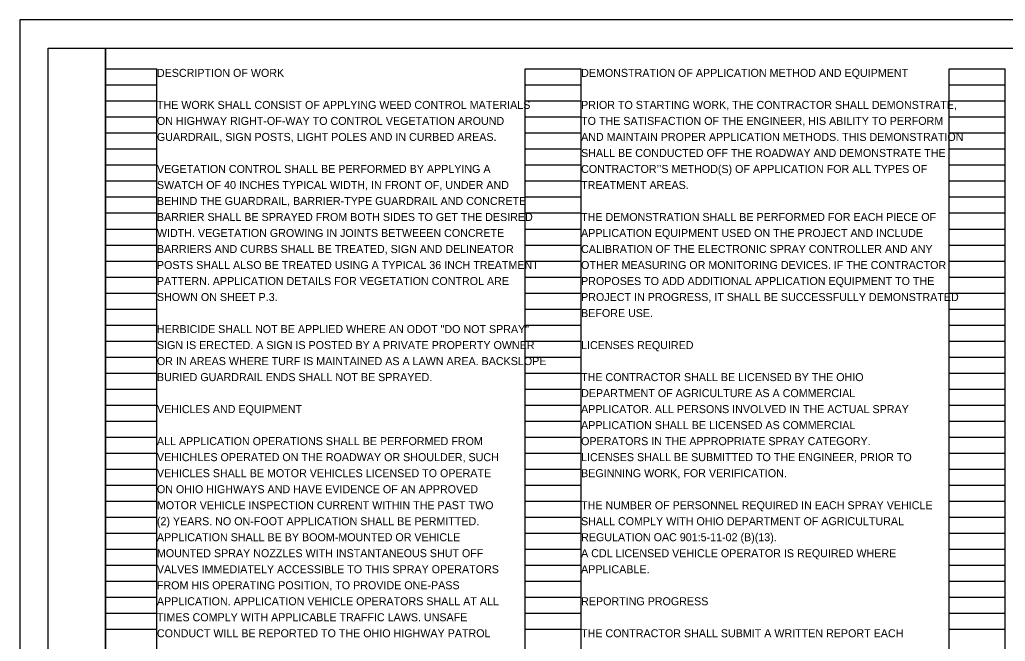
# Model space of a CAD drawing. Extents: x 0 to 34, y 0 to 22.
# Drawn here: x 0 to 17.24, y 11.13 to 22 of the extents above; entities that cross this region are included whole.
import ezdxf

# ---------------------------------------------------------------- set-up
doc = ezdxf.new("R2010")
doc.units = 0
for name, color, linetype in [('SH_Border', 7, 'Continuous'), ('SH_Cut_Line', 7, 'Continuous'), ('SH_Data', 7, 'Continuous'), ('SH_Text', 7, 'Continuous')]:
    doc.layers.add(name, color=color, linetype=linetype)

msp = doc.modelspace()

# ---------------------------------------------------------------- linework, layer by layer
at = {"layer": 'SH_Border'}
for points in [[(0.5, 21.5), (1.5, 21.5), (1.5, 0.5), (0.5, 0.5)], [(1.5, 21.5), (33.5, 21.5), (33.5, 0.5), (1.5, 0.5)]]:
    msp.add_lwpolyline(points, close=True, dxfattribs=at)
at = {"layer": 'SH_Cut_Line'}
msp.add_lwpolyline([(0, 0), (34, 0), (34, 22), (0, 22)], close=True, dxfattribs=at)
at = {"layer": 'SH_Data'}
for p, q in [((1.5, 0.98), (1.5, 21.14)), ((1.5, 21.14), (2.4, 21.14)), ((2.4, 0.98), (2.4, 21.14)), ((8.84, 0.98), (8.84, 21.14)), ((8.84, 21.14), (9.82, 21.14)), ((9.82, 0.98), (9.82, 21.14)), ((16.26, 0.98), (16.26, 21.14)), ((16.26, 21.14), (17.24, 21.14)), ((17.24, 0.98), (17.24, 21.14)), ((1.5, 20.86), (2.4, 20.86)), ((8.84, 20.86), (9.82, 20.86)), ((16.26, 20.86), (17.24, 20.86)), ((1.5, 20.58), (2.4, 20.58)), ((8.84, 20.58), (9.82, 20.58)), ((16.26, 20.58), (17.24, 20.58)), ((1.5, 20.3), (2.4, 20.3)), ((8.84, 20.3), (9.82, 20.3)), ((16.26, 20.3), (17.24, 20.3)), ((1.5, 20.02), (2.4, 20.02)), ((8.84, 20.02), (9.82, 20.02)), ((16.26, 20.02), (17.24, 20.02)), ((1.5, 19.74), (2.4, 19.74)), ((8.84, 19.74), (9.82, 19.74)), ((16.26, 19.74), (17.24, 19.74)), ((1.5, 19.46), (2.4, 19.46)), ((8.84, 19.46), (9.82, 19.46)), ((16.26, 19.46), (17.24, 19.46)), ((1.5, 19.18), (2.4, 19.18)), ((8.84, 19.18), (9.82, 19.18)), ((16.26, 19.18), (17.24, 19.18)), ((1.5, 18.9), (2.4, 18.9)), ((8.84, 18.9), (9.82, 18.9)), ((16.26, 18.9), (17.24, 18.9)), ((1.5, 18.62), (2.4, 18.62)), ((8.84, 18.62), (9.82, 18.62)), ((16.26, 18.62), (17.24, 18.62)), ((1.5, 18.34), (2.4, 18.34)), ((8.84, 18.34), (9.82, 18.34)), ((16.26, 18.34), (17.24, 18.34)), ((1.5, 18.06), (2.4, 18.06)), ((8.84, 18.06), (9.82, 18.06)), ((16.26, 18.06), (17.24, 18.06)), ((1.5, 17.78), (2.4, 17.78)), ((8.84, 17.78), (9.82, 17.78)), ((16.26, 17.78), (17.24, 17.78)), ((1.5, 17.5), (2.4, 17.5)), ((8.84, 17.5), (9.82, 17.5)), ((16.26, 17.5), (17.24, 17.5)), ((1.5, 17.22), (2.4, 17.22)), ((8.84, 17.22), (9.82, 17.22)), ((16.26, 17.22), (17.24, 17.22)), ((1.5, 16.94), (2.4, 16.94)), ((8.84, 16.94), (9.82, 16.94)), ((16.26, 16.94), (17.24, 16.94)), ((1.5, 16.66), (2.4, 16.66)), ((8.84, 16.66), (9.82, 16.66)), ((16.26, 16.66), (17.24, 16.66)), ((1.5, 16.38), (2.4, 16.38)), ((8.84, 16.38), (9.82, 16.38)), ((16.26, 16.38), (17.24, 16.38)), ((1.5, 16.1), (2.4, 16.1)), ((8.84, 16.1), (9.82, 16.1)), ((16.26, 16.1), (17.24, 16.1)), ((1.5, 15.82), (2.4, 15.82)), ((8.84, 15.82), (9.82, 15.82)), ((16.26, 15.82), (17.24, 15.82)), ((1.5, 15.54), (2.4, 15.54)), ((8.84, 15.54), (9.82, 15.54)), ((16.26, 15.54), (17.24, 15.54)), ((1.5, 15.26), (2.4, 15.26)), ((8.84, 15.26), (9.82, 15.26)), ((16.26, 15.26), (17.24, 15.26)), ((1.5, 14.98), (2.4, 14.98)), ((8.84, 14.98), (9.82, 14.98)), ((16.26, 14.98), (17.24, 14.98)), ((1.5, 14.7), (2.4, 14.7)), ((8.84, 14.7), (9.82, 14.7)), ((16.26, 14.7), (17.24, 14.7)), ((1.5, 14.42), (2.4, 14.42)), ((8.84, 14.42), (9.82, 14.42)), ((16.26, 14.42), (17.24, 14.42)), ((1.5, 14.14), (2.4, 14.14)), ((8.84, 14.14), (9.82, 14.14)), ((16.26, 14.14), (17.24, 14.14)), ((1.5, 13.86), (2.4, 13.86)), ((8.84, 13.86), (9.82, 13.86)), ((16.26, 13.86), (17.24, 13.86)), ((1.5, 13.58), (2.4, 13.58)), ((8.84, 13.58), (9.82, 13.58)), ((16.26, 13.58), (17.24, 13.58)), ((1.5, 13.3), (2.4, 13.3)), ((8.84, 13.3), (9.82, 13.3)), ((16.26, 13.3), (17.24, 13.3)), ((1.5, 13.02), (2.4, 13.02)), ((8.84, 13.02), (9.82, 13.02)), ((16.26, 13.02), (17.24, 13.02)), ((1.5, 12.74), (2.4, 12.74)), ((8.84, 12.74), (9.82, 12.74)), ((16.26, 12.74), (17.24, 12.74)), ((1.5, 12.46), (2.4, 12.46)), ((8.84, 12.46), (9.82, 12.46)), ((16.26, 12.46), (17.24, 12.46)), ((1.5, 12.18), (2.4, 12.18)), ((8.84, 12.18), (9.82, 12.18)), ((16.26, 12.18), (17.24, 12.18)), ((1.5, 11.9), (2.4, 11.9)), ((8.84, 11.9), (9.82, 11.9)), ((16.26, 11.9), (17.24, 11.9)), ((1.5, 11.62), (2.4, 11.62)), ((8.84, 11.62), (9.82, 11.62)), ((16.26, 11.62), (17.24, 11.62)), ((1.5, 11.34), (2.4, 11.34)), ((8.84, 11.34), (9.82, 11.34)), ((16.26, 11.34), (17.24, 11.34))]:
    msp.add_line(p, q, dxfattribs=at)

# ---------------------------------------------------------------- texts
at = {"layer": 'SH_Text'}
for s, p in [('DESCRIPTION OF WORK', (2.4, 21)), ('DEMONSTRATION OF APPLICATION METHOD AND EQUIPMENT', (9.82, 21)), ('THE WORK SHALL CONSIST OF APPLYING WEED CONTROL MATERIALS', (2.4, 20.44)), ('PRIOR TO STARTING WORK, THE CONTRACTOR SHALL DEMONSTRATE,', (9.82, 20.44)), ('ON HIGHWAY RIGHT-OF-WAY TO CONTROL VEGETATION AROUND', (2.4, 20.16)), ('TO THE SATISFACTION OF THE ENGINEER, HIS ABILITY TO PERFORM', (9.82, 20.16)), ('GUARDRAIL, SIGN POSTS, LIGHT POLES AND IN CURBED AREAS.', (2.4, 19.88)), ('AND MAINTAIN PROPER APPLICATION METHODS. THIS DEMONSTRATION', (9.82, 19.88)), ('SHALL BE CONDUCTED OFF THE ROADWAY AND DEMONSTRATE THE', (9.82, 19.6)), ('VEGETATION CONTROL SHALL BE PERFORMED BY APPLYING A ', (2.4, 19.32)), ('CONTRACTOR’’S METHOD(S) OF APPLICATION FOR ALL TYPES OF', (9.82, 19.32)), ('SWATCH OF 40 INCHES TYPICAL WIDTH, IN FRONT OF, UNDER AND', (2.4, 19.04)), ('TREATMENT AREAS.', (9.82, 19.04)), ('BEHIND THE GUARDRAIL, BARRIER-TYPE GUARDRAIL AND CONCRETE', (2.4, 18.76)), ('BARRIER SHALL BE SPRAYED FROM BOTH SIDES TO GET THE DESIRED', (2.4, 18.48)), ('THE DEMONSTRATION SHALL BE PERFORMED FOR EACH PIECE OF', (9.82, 18.48)), ('WIDTH. VEGETATION GROWING IN JOINTS BETWEEEN CONCRETE', (2.4, 18.2)), ('APPLICATION EQUIPMENT USED ON THE PROJECT AND INCLUDE', (9.82, 18.2)), ('BARRIERS AND CURBS SHALL BE TREATED, SIGN AND DELINEATOR', (2.4, 17.92)), ('CALIBRATION OF THE ELECTRONIC SPRAY CONTROLLER AND ANY', (9.82, 17.92)), ('POSTS SHALL ALSO BE TREATED USING A TYPICAL 36 INCH TREATMENT', (2.4, 17.64)), ('OTHER MEASURING OR MONITORING DEVICES. IF THE CONTRACTOR ', (9.82, 17.64)), ('PATTERN. APPLICATION DETAILS FOR VEGETATION CONTROL ARE ', (2.4, 17.36)), ('PROPOSES TO ADD ADDITIONAL APPLICATION EQUIPMENT TO THE', (9.82, 17.36)), ('SHOWN ON SHEET P.3.', (2.4, 17.08)), ('PROJECT IN PROGRESS, IT SHALL BE SUCCESSFULLY DEMONSTRATED', (9.82, 17.08)), ('BEFORE USE.', (9.82, 16.8)), ('HERBICIDE SHALL NOT BE APPLIED WHERE AN ODOT "DO NOT SPRAY"', (2.4, 16.52)), ('SIGN IS ERECTED. A SIGN IS POSTED BY A PRIVATE PROPERTY OWNER', (2.4, 16.24)), ('LICENSES REQUIRED', (9.82, 16.24)), ('OR IN AREAS WHERE TURF IS MAINTAINED AS A LAWN AREA. BACKSLOPE', (2.4, 15.96)), ('BURIED GUARDRAIL ENDS SHALL NOT BE SPRAYED.', (2.4, 15.68)), ('THE CONTRACTOR SHALL BE LICENSED BY THE OHIO', (9.82, 15.68)), ('DEPARTMENT OF AGRICULTURE AS A COMMERCIAL', (9.82, 15.4)), ('VEHICLES AND EQUIPMENT', (2.4, 15.12)), ('APPLICATOR. ALL PERSONS INVOLVED IN THE ACTUAL SPRAY', (9.82, 15.12)), ('APPLICATION SHALL BE LICENSED AS COMMERCIAL', (9.82, 14.84)), ('ALL APPLICATION OPERATIONS SHALL BE PERFORMED FROM', (2.4, 14.56)), ('OPERATORS IN THE APPROPRIATE SPRAY CATEGORY.', (9.82, 14.56)), ('VEHICHLES OPERATED ON THE ROADWAY OR SHOULDER, SUCH', (2.4, 14.28)), ('LICENSES SHALL BE SUBMITTED TO THE ENGINEER, PRIOR TO', (9.82, 14.28)), ('VEHICLES SHALL BE MOTOR VEHICLES LICENSED TO OPERATE', (2.4, 14)), ('BEGINNING WORK, FOR VERIFICATION.', (9.82, 14)), ('ON OHIO HIGHWAYS AND HAVE EVIDENCE OF AN APPROVED ', (2.4, 13.72)), ('MOTOR VEHICLE INSPECTION CURRENT WITHIN THE PAST TWO', (2.4, 13.44)), ('THE NUMBER OF PERSONNEL REQUIRED IN EACH SPRAY VEHICLE', (9.82, 13.44)), ('(2) YEARS. NO ON-FOOT APPLICATION SHALL BE PERMITTED.', (2.4, 13.16)), ('SHALL COMPLY WITH OHIO DEPARTMENT OF AGRICULTURAL', (9.82, 13.16)), ('APPLICATION SHALL BE BY BOOM-MOUNTED OR VEHICLE ', (2.4, 12.88)), ('REGULATION OAC 901:5-11-02 (B)(13).', (9.82, 12.88)), ('MOUNTED SPRAY NOZZLES WITH INSTANTANEOUS SHUT OFF ', (2.4, 12.6)), ('A CDL LICENSED VEHICLE OPERATOR IS REQUIRED WHERE', (9.82, 12.6)), ('VALVES IMMEDIATELY ACCESSIBLE TO THIS SPRAY OPERATORS ', (2.4, 12.32)), ('APPLICABLE.', (9.82, 12.32)), ('FROM HIS OPERATING POSITION, TO PROVIDE ONE-PASS ', (2.4, 12.04)), ('APPLICATION. APPLICATION VEHICLE OPERATORS SHALL AT ALL', (2.4, 11.76)), ('REPORTING PROGRESS', (9.82, 11.76)), ('TIMES COMPLY WITH APPLICABLE TRAFFIC LAWS. UNSAFE ', (2.4, 11.48)), ('CONDUCT WILL BE REPORTED TO THE OHIO HIGHWAY PATROL', (2.4, 11.2)), ('THE CONTRACTOR SHALL SUBMIT A WRITTEN REPORT EACH', (9.82, 11.2))]:
    msp.add_text(s, height=0.14, dxfattribs=at).set_placement(p)

doc.saveas('drawing.dxf')
